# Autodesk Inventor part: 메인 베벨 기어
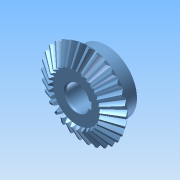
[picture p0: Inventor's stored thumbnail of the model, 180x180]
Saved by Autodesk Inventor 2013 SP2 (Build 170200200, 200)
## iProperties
Created: 2026-07
Part Number: 메인 베벨 기어
Material: Generic
Document SubType Name: Modeling
Designer: 601
Density: 1 g/cm^3
Author: 601
변환 표준: STEP AP214IS
전처리기: Build: 200, Release: 2013 SP2 Update 6 - Date: Thu 07/17/2014
전송 단위: 밀리미터
불확실성: 0.01
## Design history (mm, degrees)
node "메인 베벨기어1"
body "Solid1"
node "기준1"
